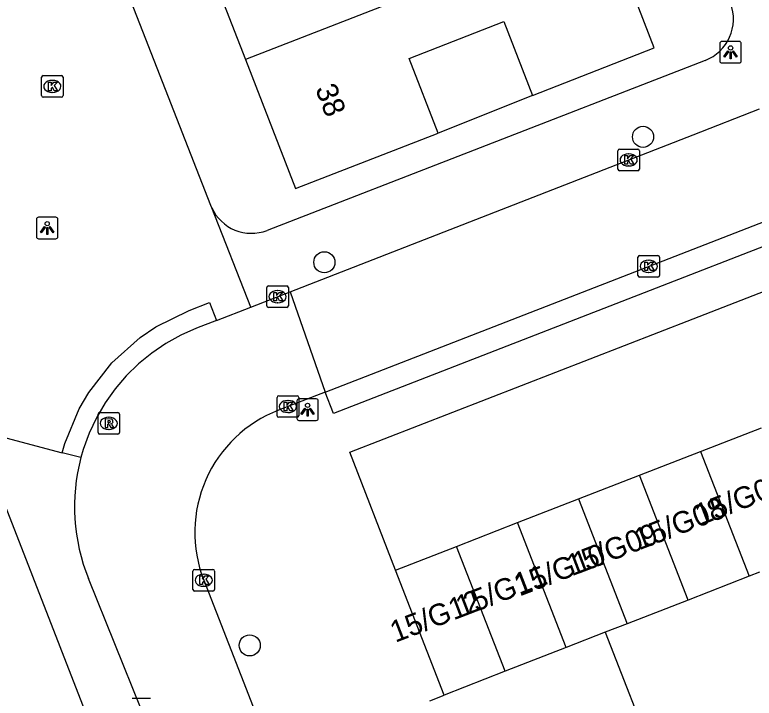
# Model space of a CAD drawing. Extents: x 159689 to 160786, y 387323 to 388339.
# Drawn here: x 159968.51 to 160002.84, y 387832.23 to 387863.94 of the extents above; entities that cross this region are included whole.
import ezdxf

# ---------------------------------------------------------------- set-up
doc = ezdxf.new("R2010")
doc.units = 0
for name, color, linetype in [('IMGEO_Boom', 7, 'Continuous'), ('IMGEO_Erf', 7, 'Continuous'), ('IMGEO_Kolk', 7, 'Continuous'), ('IMGEO_Lichtpunt', 7, 'Continuous'), ('IMGEO_Pand', 7, 'Continuous'), ('IMGEO_Pand_nummerreeks', 7, 'Continuous'), ('IMGEO_Rijbaan_lokaal_open', 7, 'Continuous'), ('IMGEO_Rioolput', 7, 'Continuous'), ('IMGEO_Voetpad_open', 7, 'Continuous')]:
    doc.layers.add(name, color=color, linetype=linetype)

msp = doc.modelspace()

# ---------------------------------------------------------------- linework, layer by layer
at = {"layer": 'IMGEO_Boom'}
for centre in [(159997.677, 387858.28), (159982.885, 387852.458), (159979.42, 387834.679)]:
    msp.add_circle(centre, 0.489, dxfattribs=at)
at = {"layer": 'IMGEO_Erf'}
msp.add_lwpolyline([(159992.546, 387860.204), (159988.172, 387858.447)], dxfattribs=at)
at = {"layer": 'IMGEO_Kolk'}
for p, q in [((159969.755, 387860.193), (159969.755, 387861.045)), ((159969.83, 387861.119), (159970.682, 387861.119)), ((159970.756, 387861.045), (159970.756, 387860.193)), ((159970.243, 387860.899), (159970.268, 387860.899)), ((159970.266, 387860.339), (159970.241, 387860.339)), ((159970.682, 387860.119), (159969.83, 387860.119)), ((159996.51, 387856.781), (159996.51, 387857.633)), ((159996.585, 387857.707), (159997.437, 387857.707)), ((159996.998, 387857.487), (159997.023, 387857.487)), ((159997.511, 387857.633), (159997.511, 387856.781)), ((159997.021, 387856.927), (159996.996, 387856.927)), ((159997.437, 387856.707), (159996.585, 387856.707)), ((159997.443, 387851.844), (159997.443, 387852.696)), ((159997.518, 387852.77), (159998.37, 387852.77)), ((159998.444, 387852.696), (159998.444, 387851.844)), ((159997.931, 387852.55), (159997.956, 387852.55)), ((159997.954, 387851.99), (159997.929, 387851.99)), ((159998.37, 387851.77), (159997.518, 387851.77)), ((159980.289, 387851.362), (159981.141, 387851.362)), ((159980.214, 387850.436), (159980.214, 387851.288)), ((159980.702, 387851.142), (159980.727, 387851.142)), ((159981.215, 387851.288), (159981.215, 387850.436)), ((159981.141, 387850.362), (159980.289, 387850.362)), ((159980.725, 387850.582), (159980.7, 387850.582)), ((159980.692, 387845.338), (159980.692, 387846.19)), ((159980.767, 387846.264), (159981.619, 387846.264)), ((159981.693, 387846.19), (159981.693, 387845.338)), ((159981.18, 387846.044), (159981.205, 387846.044)), ((159981.203, 387845.484), (159981.178, 387845.484)), ((159981.619, 387845.264), (159980.767, 387845.264)), ((159976.785, 387837.275), (159976.785, 387838.127)), ((159976.86, 387838.201), (159977.712, 387838.201)), ((159977.273, 387837.981), (159977.298, 387837.981)), ((159977.786, 387838.127), (159977.786, 387837.275)), ((159977.296, 387837.421), (159977.271, 387837.421)), ((159977.712, 387837.201), (159976.86, 387837.201)), ((159973.955, 387832.228), (159974.807, 387832.228))]:
    msp.add_line(p, q, dxfattribs=at)
for points in [[(159969.755, 387860.193), (159969.755, 387861.045)], [(159969.83, 387861.119), (159970.682, 387861.119)], [(159970.756, 387861.045), (159970.756, 387860.193)], [(159970.076, 387860.819), (159970.199, 387860.819), (159970.199, 387860.668), (159970.329, 387860.819), (159970.493, 387860.819), (159970.347, 387860.668), (159970.5, 387860.419), (159970.348, 387860.419), (159970.263, 387860.583), (159970.199, 387860.516), (159970.199, 387860.419), (159970.076, 387860.419), (159970.076, 387860.819)], [(159970.682, 387860.119), (159969.83, 387860.119)], [(159996.51, 387856.781), (159996.51, 387857.633)], [(159996.585, 387857.707), (159997.437, 387857.707)], [(159997.511, 387857.633), (159997.511, 387856.781)], [(159996.831, 387857.407), (159996.954, 387857.407), (159996.954, 387857.256), (159997.084, 387857.407), (159997.248, 387857.407), (159997.102, 387857.256), (159997.255, 387857.007), (159997.103, 387857.007), (159997.018, 387857.171), (159996.954, 387857.104), (159996.954, 387857.007), (159996.831, 387857.007), (159996.831, 387857.407)], [(159997.437, 387856.707), (159996.585, 387856.707)], [(159997.443, 387851.844), (159997.443, 387852.696)], [(159997.518, 387852.77), (159998.37, 387852.77)], [(159998.444, 387852.696), (159998.444, 387851.844)], [(159997.764, 387852.47), (159997.887, 387852.47), (159997.887, 387852.319), (159998.017, 387852.47), (159998.181, 387852.47), (159998.035, 387852.319), (159998.188, 387852.07), (159998.036, 387852.07), (159997.951, 387852.234), (159997.887, 387852.167), (159997.887, 387852.07), (159997.764, 387852.07), (159997.764, 387852.47)], [(159998.37, 387851.77), (159997.518, 387851.77)], [(159980.289, 387851.362), (159981.141, 387851.362)], [(159980.214, 387850.436), (159980.214, 387851.288)], [(159980.535, 387851.062), (159980.658, 387851.062), (159980.658, 387850.911), (159980.788, 387851.062), (159980.952, 387851.062), (159980.806, 387850.911), (159980.959, 387850.662), (159980.807, 387850.662), (159980.722, 387850.826), (159980.658, 387850.759), (159980.658, 387850.662), (159980.535, 387850.662), (159980.535, 387851.062)], [(159981.215, 387851.288), (159981.215, 387850.436)], [(159981.141, 387850.362), (159980.289, 387850.362)], [(159980.692, 387845.338), (159980.692, 387846.19)], [(159980.767, 387846.264), (159981.619, 387846.264)], [(159981.693, 387846.19), (159981.693, 387845.338)], [(159981.013, 387845.964), (159981.136, 387845.964), (159981.136, 387845.813), (159981.266, 387845.964), (159981.43, 387845.964), (159981.284, 387845.813), (159981.437, 387845.564), (159981.285, 387845.564), (159981.2, 387845.728), (159981.136, 387845.661), (159981.136, 387845.564), (159981.013, 387845.564), (159981.013, 387845.964)], [(159981.619, 387845.264), (159980.767, 387845.264)], [(159976.785, 387837.275), (159976.785, 387838.127)], [(159976.86, 387838.201), (159977.712, 387838.201)], [(159977.786, 387838.127), (159977.786, 387837.275)], [(159977.106, 387837.901), (159977.229, 387837.901), (159977.229, 387837.75), (159977.359, 387837.901), (159977.523, 387837.901), (159977.377, 387837.75), (159977.53, 387837.501), (159977.378, 387837.501), (159977.293, 387837.665), (159977.229, 387837.598), (159977.229, 387837.501), (159977.106, 387837.501), (159977.106, 387837.901)], [(159977.712, 387837.201), (159976.86, 387837.201)], [(159973.955, 387832.228), (159974.807, 387832.228)]]:
    msp.add_lwpolyline(points, dxfattribs=at)
for centre, start, end in [((159969.832, 387861.043), 91.552, 178.448), ((159969.832, 387861.043), 91.552, 178.448), ((159970.68, 387861.043), 1.552, 88.448), ((159970.68, 387861.043), 1.552, 88.448), ((159969.832, 387860.195), 181.552, 268.448), ((159969.832, 387860.195), 181.552, 268.448), ((159970.68, 387860.195), 271.552, 358.448), ((159970.68, 387860.195), 271.552, 358.448), ((159996.587, 387857.631), 91.552, 178.448), ((159996.587, 387857.631), 91.552, 178.448), ((159997.435, 387857.631), 1.552, 88.448), ((159997.435, 387857.631), 1.552, 88.448), ((159996.587, 387856.783), 181.552, 268.448), ((159996.587, 387856.783), 181.552, 268.448), ((159997.435, 387856.783), 271.552, 358.448), ((159997.435, 387856.783), 271.552, 358.448), ((159997.52, 387852.694), 91.552, 178.448), ((159997.52, 387852.694), 91.552, 178.448), ((159998.368, 387852.694), 1.552, 88.448), ((159998.368, 387852.694), 1.552, 88.448), ((159997.52, 387851.846), 181.552, 268.448), ((159997.52, 387851.846), 181.552, 268.448), ((159998.368, 387851.846), 271.552, 358.448), ((159998.368, 387851.846), 271.552, 358.448), ((159980.291, 387851.286), 91.552, 178.448), ((159980.291, 387851.286), 91.552, 178.448), ((159981.139, 387851.286), 1.552, 88.448), ((159981.139, 387851.286), 1.552, 88.448), ((159980.291, 387850.438), 181.552, 268.448), ((159980.291, 387850.438), 181.552, 268.448), ((159981.139, 387850.438), 271.552, 358.448), ((159981.139, 387850.438), 271.552, 358.448), ((159980.769, 387846.188), 91.552, 178.448), ((159980.769, 387846.188), 91.552, 178.448), ((159981.617, 387846.188), 1.552, 88.448), ((159981.617, 387846.188), 1.552, 88.448), ((159980.769, 387845.34), 181.552, 268.448), ((159980.769, 387845.34), 181.552, 268.448), ((159981.617, 387845.34), 271.552, 358.448), ((159981.617, 387845.34), 271.552, 358.448), ((159976.862, 387838.125), 91.552, 178.448), ((159976.862, 387838.125), 91.552, 178.448), ((159977.71, 387838.125), 1.552, 88.448), ((159977.71, 387838.125), 1.552, 88.448), ((159976.862, 387837.277), 181.552, 268.448), ((159976.862, 387837.277), 181.552, 268.448), ((159977.71, 387837.277), 271.552, 358.448), ((159977.71, 387837.277), 271.552, 358.448)]:
    msp.add_arc(centre, 0.0765, start, end, dxfattribs=at)
for centre, major_axis, ratio, start_param, end_param in [((159970.242, 387860.619), (-0.387, 0.002), 0.722429, 4.712389, 7.853982), ((159970.267, 387860.619), (-0.39, 0.002), 0.717154, 1.570796, 4.712389), ((159996.997, 387857.207), (-0.387, 0.002), 0.722429, 4.712389, 7.853982), ((159997.022, 387857.207), (-0.39, 0.002), 0.717154, 1.570796, 4.712389), ((159997.93, 387852.27), (-0.387, 0.002), 0.722429, 4.712389, 7.853982), ((159997.955, 387852.27), (-0.39, 0.002), 0.717154, 1.570796, 4.712389), ((159980.701, 387850.862), (-0.387, 0.002), 0.722429, 4.712389, 7.853982), ((159980.726, 387850.862), (-0.39, 0.002), 0.717154, 1.570796, 4.712389), ((159981.179, 387845.764), (-0.387, 0.002), 0.722429, 4.712389, 7.853982), ((159981.204, 387845.764), (-0.39, 0.002), 0.717154, 1.570796, 4.712389), ((159977.272, 387837.701), (-0.387, 0.002), 0.722429, 4.712389, 7.853982), ((159977.297, 387837.701), (-0.39, 0.002), 0.717154, 1.570796, 4.712389)]:
    msp.add_ellipse(centre, major_axis=major_axis, ratio=ratio, start_param=start_param, end_param=end_param, dxfattribs=at)
at = {"layer": 'IMGEO_Lichtpunt'}
for p, q in [((160002.142, 387862.703), (160001.334, 387862.703)), ((160002.142, 387862.703), (160001.334, 387862.703)), ((160001.24, 387862.608), (160001.24, 387861.801)), ((160001.24, 387862.608), (160001.24, 387861.801)), ((160002.236, 387861.801), (160002.236, 387862.608)), ((160002.236, 387861.801), (160002.236, 387862.608)), ((160001.334, 387861.707), (160002.142, 387861.707)), ((160001.334, 387861.707), (160002.142, 387861.707)), ((159969.519, 387854.451), (159969.519, 387853.644)), ((159969.519, 387854.451), (159969.519, 387853.644)), ((159970.421, 387854.546), (159969.613, 387854.546)), ((159970.421, 387854.546), (159969.613, 387854.546)), ((159970.515, 387853.644), (159970.515, 387854.451)), ((159970.515, 387853.644), (159970.515, 387854.451)), ((159969.613, 387853.55), (159970.421, 387853.55)), ((159969.613, 387853.55), (159970.421, 387853.55)), ((159981.608, 387846.021), (159981.608, 387845.214)), ((159981.608, 387846.021), (159981.608, 387845.214)), ((159982.51, 387846.116), (159981.702, 387846.116)), ((159982.51, 387846.116), (159981.702, 387846.116)), ((159982.604, 387845.214), (159982.604, 387846.021)), ((159982.604, 387845.214), (159982.604, 387846.021)), ((159981.702, 387845.12), (159982.51, 387845.12)), ((159981.702, 387845.12), (159982.51, 387845.12))]:
    msp.add_line(p, q, dxfattribs=at)
for points in [[(160001.614, 387862.272), (160001.653, 387862.244), (160001.465, 387861.982), (160001.427, 387862.009), (160001.614, 387862.272)], [(160001.716, 387862.224), (160001.763, 387862.224), (160001.763, 387861.902), (160001.716, 387861.902), (160001.716, 387862.224)], [(160001.826, 387862.244), (160001.864, 387862.271), (160002.051, 387862.009), (160002.012, 387861.981), (160001.826, 387862.244)], [(159969.893, 387854.115), (159969.932, 387854.087), (159969.744, 387853.825), (159969.706, 387853.852), (159969.893, 387854.115)], [(159969.995, 387854.067), (159970.042, 387854.067), (159970.042, 387853.745), (159969.995, 387853.745), (159969.995, 387854.067)], [(159970.105, 387854.087), (159970.143, 387854.114), (159970.33, 387853.852), (159970.291, 387853.824), (159970.105, 387854.087)], [(159981.982, 387845.685), (159982.021, 387845.657), (159981.833, 387845.395), (159981.795, 387845.422), (159981.982, 387845.685)], [(159982.084, 387845.637), (159982.131, 387845.637), (159982.131, 387845.315), (159982.084, 387845.315), (159982.084, 387845.637)], [(159982.194, 387845.657), (159982.232, 387845.684), (159982.419, 387845.422), (159982.38, 387845.394), (159982.194, 387845.657)]]:
    msp.add_lwpolyline(points, dxfattribs=at)
for centre in [(160001.739, 387862.406), (159970.018, 387854.249), (159982.107, 387845.819)]:
    msp.add_circle(centre, 0.0994, dxfattribs=at)
for centre, start, end in [((160001.334, 387862.608), 90, 180), ((160001.334, 387862.608), 90, 180), ((160002.142, 387862.608), 0, 90), ((160002.142, 387862.608), 0, 90), ((160001.334, 387861.801), 180, 270), ((160001.334, 387861.801), 180, 270), ((160002.142, 387861.801), 270, 0), ((160002.142, 387861.801), 270, 360), ((159969.613, 387854.451), 90, 180), ((159969.613, 387854.451), 90, 180), ((159970.421, 387854.451), 0, 90), ((159970.421, 387854.451), 0, 90), ((159969.613, 387853.644), 180, 270), ((159969.613, 387853.644), 180, 270), ((159970.421, 387853.644), 270, 0), ((159970.421, 387853.644), 270, 360), ((159981.702, 387846.021), 90, 180), ((159981.702, 387846.021), 90, 180), ((159982.51, 387846.021), 0, 90), ((159982.51, 387846.021), 0, 90), ((159981.702, 387845.214), 180, 270), ((159981.702, 387845.214), 180, 270), ((159982.51, 387845.214), 270, 0), ((159982.51, 387845.214), 270, 360)]:
    msp.add_arc(centre, 0.0946, start, end, dxfattribs=at)
at = {"layer": 'IMGEO_Pand'}
for points in [[(159992.546, 387860.204), (159998.192, 387862.41), (159995.906, 387868.349)], [(159976.934, 387867.751), (159979.217, 387861.869)], [(159985.793, 387864.422), (159979.217, 387861.869)], [(159988.172, 387858.447), (159986.825, 387861.918), (159991.218, 387863.624), (159992.546, 387860.204)], [(159979.217, 387861.869), (159981.544, 387855.874), (159988.172, 387858.447)], [(160000.344, 387843.68), (160003.174, 387844.781)], [(159997.514, 387842.579), (160000.344, 387843.68)], [(160000.344, 387843.68), (160002.597, 387837.888)], [(159994.684, 387841.478), (159997.514, 387842.579)], [(159999.768, 387836.784), (159997.514, 387842.579)], [(159991.853, 387840.376), (159994.684, 387841.478)], [(159994.684, 387841.478), (159996.939, 387835.681)], [(159989.023, 387839.275), (159991.853, 387840.376)], [(159994.109, 387834.579), (159991.853, 387840.376)], [(159986.193, 387838.174), (159989.023, 387839.275)], [(159991.279, 387833.477), (159989.023, 387839.275)], [(159988.449, 387832.375), (159986.193, 387838.174)], [(160003.08, 387838.076), (160002.597, 387837.888)], [(160002.597, 387837.888), (159999.768, 387836.784)], [(159999.768, 387836.784), (159996.939, 387835.681)], [(159996.939, 387835.681), (159995.926, 387835.286)], [(159995.926, 387835.286), (159994.109, 387834.579)], [(159995.926, 387835.286), (159998.285, 387829.225), (159997.278, 387828.833)], [(159994.109, 387834.579), (159991.279, 387833.477)], [(159991.279, 387833.477), (159988.449, 387832.375)], [(159987.782, 387832.114), (159988.449, 387832.375)]]:
    msp.add_lwpolyline(points, dxfattribs=at)
at = {"layer": 'IMGEO_Rijbaan_lokaal_open'}
for points in [[(159977.657, 387854.991), (159977.619, 387855.089), (159964.689, 387888.113)], [(159982.917, 387846.434), (160000, 387853.068), (160013.528, 387858.321), (160018.212, 387860.145)], [(159981.294, 387851.087), (160000, 387858.37), (160003.091, 387859.574)], [(159979.465, 387850.375), (159977.657, 387854.991)], [(159979.465, 387850.375), (159981.294, 387851.087)], [(159981.294, 387851.087), (159982.917, 387846.434)], [(159970.713, 387843.622), (159970.838, 387844.055), (159971.507, 387845.662), (159971.949, 387846.418), (159973.025, 387847.798), (159974.33, 387848.965), (159975.056, 387849.456), (159976.604, 387850.226), (159977.558, 387850.598), (159977.884, 387849.759)], [(159977.884, 387849.759), (159979.465, 387850.375)], [(159977.884, 387849.759), (159976.95, 387849.395), (159976.223, 387849.073), (159975.527, 387848.688), (159974.868, 387848.242), (159974.252, 387847.739), (159973.683, 387847.183), (159973.166, 387846.578), (159972.706, 387845.93), (159972.305, 387845.243), (159971.967, 387844.523), (159971.694, 387843.776), (159971.583, 387843.391)], [(159982.917, 387846.434), (159980.753, 387845.594)], [(159966.687, 387844.688), (159970.713, 387843.622)], [(159976.996, 387825.036), (159974.384, 387831.725), (159971.935, 387837.777)], [(159977.284, 387837.705), (159988.06, 387810.061)]]:
    msp.add_lwpolyline(points, dxfattribs=at)
for centre, radius, start, end in [((159982.957, 387839.918), 6.089, 111.2201, 201.3072), ((159980.189, 387841.113), 8.903, 165.1721, 202.0035)]:
    msp.add_arc(centre, radius, start, end, dxfattribs=at)
at = {"layer": 'IMGEO_Rioolput'}
for p, q in [((159972.452, 387845.485), (159973.304, 387845.485)), ((159972.377, 387844.559), (159972.377, 387845.411)), ((159972.865, 387845.265), (159972.89, 387845.265)), ((159973.378, 387845.411), (159973.378, 387844.559)), ((159973.304, 387844.485), (159972.452, 387844.485)), ((159972.888, 387844.705), (159972.863, 387844.705))]:
    msp.add_line(p, q, dxfattribs=at)
for points in [[(159972.452, 387845.485), (159973.304, 387845.485)], [(159972.377, 387844.559), (159972.377, 387845.411)], [(159972.966, 387845.183), (159972.714, 387845.185), (159972.714, 387844.785)], [(159973.378, 387845.411), (159973.378, 387844.559)], [(159972.714, 387844.785), (159972.838, 387844.785), (159972.838, 387844.947), (159972.849, 387844.947)], [(159972.892, 387845.104), (159972.838, 387845.104), (159972.838, 387845.023)], [(159972.838, 387845.023), (159972.89, 387845.023)], [(159972.896, 387844.918), (159972.967, 387844.785), (159973.107, 387844.785), (159973.042, 387844.911)], [(159973.304, 387844.485), (159972.452, 387844.485)]]:
    msp.add_lwpolyline(points, dxfattribs=at)
for centre, radius, start, end in [((159972.454, 387845.409), 0.0765, 91.552, 178.448), ((159972.454, 387845.409), 0.0765, 91.552, 178.448), ((159973.302, 387845.409), 0.0765, 1.552, 88.448), ((159973.302, 387845.409), 0.0765, 1.552, 88.448), ((159972.965, 387845.073), 0.109, 350.3612, 89.416), ((159972.848, 387844.894), 0.0533, 26.0293, 88.6989), ((159972.874, 387845.212), 0.19, 274.7715, 282.9687), ((159972.898, 387845.008), 0.0964, 77.0061, 93.1865), ((159972.912, 387845.065), 0.0378, 276.6634, 79.6772), ((159972.963, 387845.073), 0.112, 277.5842, 350.9817), ((159972.947, 387844.858), 0.108, 29.5134, 73.7905), ((159972.454, 387844.561), 0.0765, 181.552, 268.448), ((159972.454, 387844.561), 0.0765, 181.552, 268.448), ((159973.302, 387844.561), 0.0765, 271.552, 358.448), ((159973.302, 387844.561), 0.0765, 271.552, 358.448)]:
    msp.add_arc(centre, radius, start, end, dxfattribs=at)
for centre, major_axis, ratio, start_param, end_param in [((159972.864, 387844.985), (-0.387, 0.002), 0.722429, 4.712389, 7.853982), ((159972.889, 387844.985), (-0.39, 0.002), 0.717154, 1.570796, 4.712389)]:
    msp.add_ellipse(centre, major_axis=major_axis, ratio=ratio, start_param=start_param, end_param=end_param, dxfattribs=at)
at = {"layer": 'IMGEO_Voetpad_open'}
for points in [[(160000.556, 387861.822), (160000, 387861.606), (159980.233, 387853.939)], [(160018.212, 387860.145), (160018.599, 387859.148), (159983.304, 387845.437), (159982.917, 387846.434)], [(159986.193, 387838.174), (159984.066, 387843.64), (160000, 387849.829), (160019.276, 387857.317), (160021.405, 387851.848)], [(159973.264, 387827.809), (159966.687, 387844.688)], [(159971.583, 387843.391), (159970.713, 387843.622)]]:
    msp.add_lwpolyline(points, dxfattribs=at)
for centre, radius, start, end in [((159999.81, 387863.747), 2.064, 291.1758, 20.8033), ((159979.5, 387855.825), 2.023, 204.3446, 291.2266)]:
    msp.add_arc(centre, radius, start, end, dxfattribs=at)

# ---------------------------------------------------------------- texts
at = {"layer": 'IMGEO_Pand_nummerreeks'}
for s, rotation, p in [('38', 291.2164, (159982.448, 387860.509)), ('15/G07', 21.0733, (160000.334, 387840.235)), ('15/G08', 21.0733, (159997.496, 387839.089)), ('15/G09', 21.0733, (159994.371, 387837.883)), ('15/G10', 21.0733, (159991.944, 387836.943)), ('15/G11', 21.0733, (159989.226, 387835.971)), ('15/G12', 21.0733, (159986.177, 387834.796))]:
    msp.add_text(s, height=1, rotation=rotation, dxfattribs=at).set_placement(p)

doc.saveas('drawing.dxf')
